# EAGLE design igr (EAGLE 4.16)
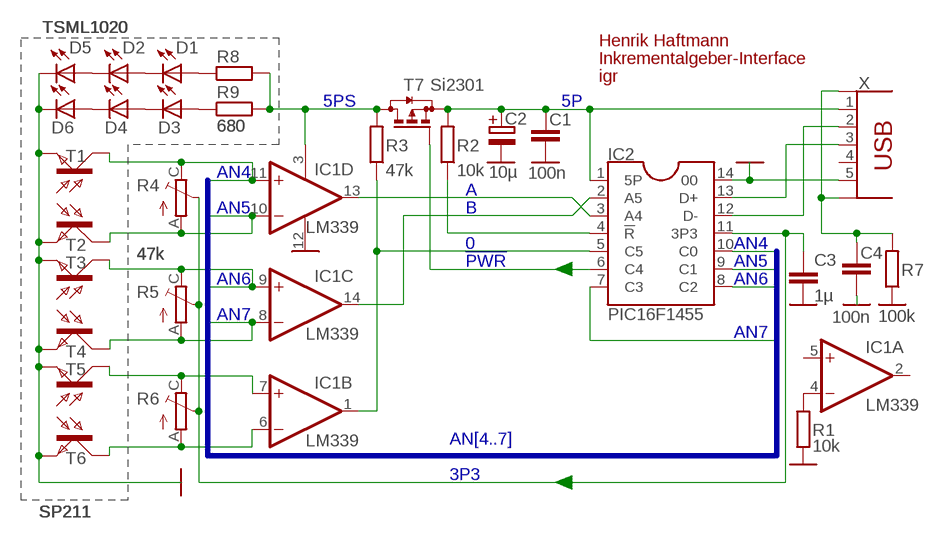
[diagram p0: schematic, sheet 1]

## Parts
C1  100n  C0603  [0603@1]
C2  10µ  E01-5  [E01-5]
C3  1µ  C0603  [0603@1]
C4  100n  C0603  [0603@1]
D1  TSML1020  LED0603  [0603]
D2  TSML1020  LED0603  [0603]
D3  TSML1020  LED0603  [0603]
D4  TSML1020  LED0603  [0603]
D5  TSML1020  LED0603  [0603]
D6  TSML1020  LED0603  [0603]
IC1  LM339  LM339N  [DIL14]
IC2  PIC16F1455  PIC16F1455-I/P  [DIL14]
R1  10k  R0603  [0603@1]
R2  10k  R0603  [0603@1]
R3  47k  R0603  [0603@1]
R4  47k  RTRIM  [RTRIM-RFT]
R5  47k  RTRIM  [RTRIM-RFT]
R6  47k  RTRIM  [RTRIM-RFT]
R7  100k  R0603  [0603@1]
R8  680  R0603  [0603@1]
R9  680  R0603  [0603@1]
T1  SP211  BPX81  [BPX81]
T2  SP211  BPX81  [BPX81]
T3  SP211  BPX81  [BPX81]
T4  SP211  BPX81  [BPX81]
T5  SP211  BPX81  [BPX81]
T6  SP211  BPX81  [BPX81]
T7  Si2301  PMOS  [SOT23]
X  USB5+2MINI  [USB-MINIB]

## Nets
0: IC1.1(B:OUT) IC2.5(C5) R3.1
3P3: C3.1 IC2.11(3P3) R4.B(S) R5.B(S) R6.B(S)
5P: C1.1 C2.+ IC2.1(5P) R2.2 T7.2(S) X.1
5PS: IC1.3(P:V+) R3.2 R8.2 R9.2 T7.3(D)
!PWR: IC2.6(C4) T7.1(G)
A: IC1.13(D:OUT) IC2.3(A4)
AN4: IC1.11(D:+IN) IC2.10(C0) R4.C(E) T1.C
AN5: IC1.10(D:-IN) IC2.9(C1) R4.A T2.C
AN6: IC1.9(C:+IN) IC2.8(C2) R5.C(E) T3.C
AN7: IC1.8(C:-IN) IC2.7(C3) R5.A T4.C
B: IC1.14(C:OUT) IC2.2(A5)
D+: IC2.13(D+) X.3
D-: IC2.12(D-) X.2
GND: C1.2 C2.- C3.2 C4.2 D5.2(K) D6.2(K) IC1.12(P:GND) IC2.14 R1.2 R7.1 T1.E T2.E T3.E T4.E T5.E T6.E X.5
N$5: IC1.4(A:-IN) R1.1
N$10: IC1.7(B:+IN) R6.C(E) T5.C
N$11: IC1.6(B:-IN) R6.A T6.C
N$14: D1.1(A) R8.1
N$15: D1.2(K) D2.1(A)
N$16: D2.2(K) D5.1(A)
N$17: D3.1(A) R9.1
N$18: D3.2(K) D4.1(A)
N$19: D4.2(K) D6.1(A)
N$26: IC2.4(!R) R2.1
PE: C4.1 R7.2 X.M1(S) X.M2(S)
Unconnected: IC1.2(A:OUT) IC1.5(A:+IN) X.4

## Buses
AN[4..7]

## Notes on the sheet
- Henrik Haftmann
- Inkrementalgeber-Interface

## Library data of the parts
C1 C3 C4 = fu:C: Kondensator
C2 = fu:E: Elektrolytkondensator, gepolt
D1-D6 = fu:LED: Leuchtdiode
IC1 = linear:LM339: Low Power Low Offset Voltage Quad Comparators with open collector; LM139/LM239/LM339/LM2901/LM3302
IC2 = hs-ul:PIC16F145*: 8-bit-Mikrocontroller mit USB Gezeichnet in Gehäuse-Anordnung, für USB-PCS500-Adapter. Typen: PIC16F1454 PIC16F1455 (mit ADU, DAU und 2x Analogvergleicher) Jeweils 8K x 14bit Flash, 1K RAM Features Benötigt keinen Quarz, interne PLL Benötigt keine USB-Serienwiderstände 3,3-V-Spannungsregler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
R1-R3 R7-R9 = fu:R: Widerstand
R4-R6 = us1:RTRIM: Einstell-Potenziometer
T1-T6 = opto-trans-siemens:BPX81: PHOTO TRANSISTOR
T7 = w:PMOS: p-Kanal-MOSFET
X = w:USB5+2: USB-Buchse (A oder B) Standardausführung der USB-Version 1.0, 4-polig Mit 2 Schirmanschlüssen

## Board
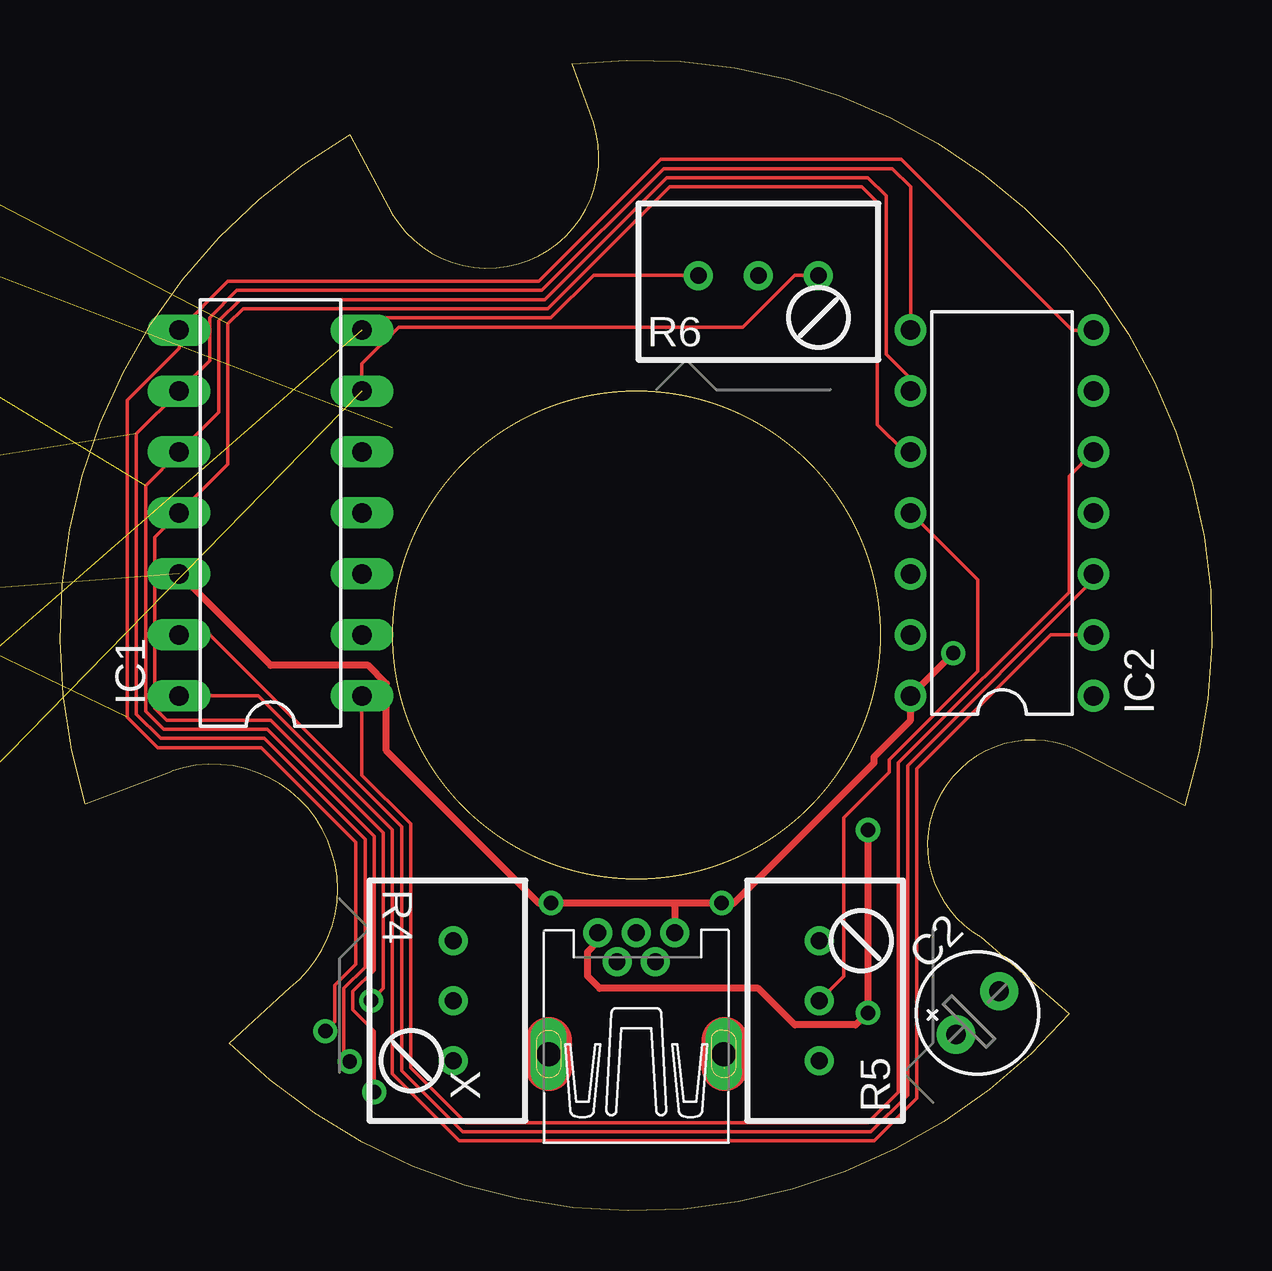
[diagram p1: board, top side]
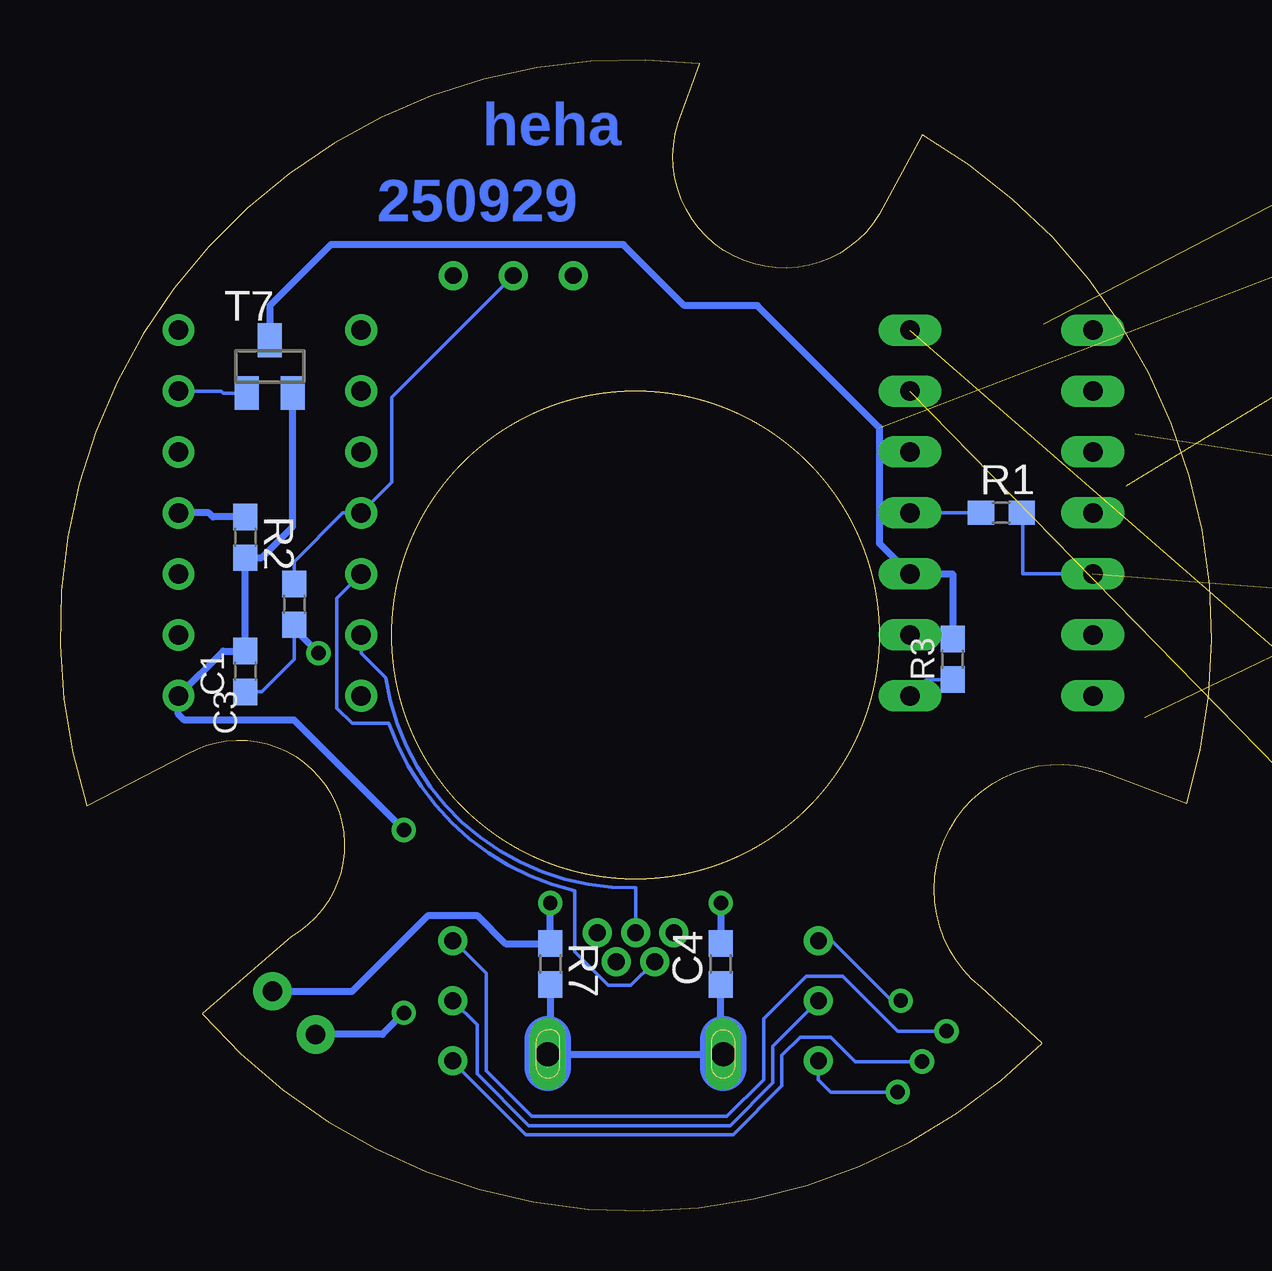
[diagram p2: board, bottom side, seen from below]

Size 47.99 x 47.96 mm. Coordinates in mm from the lower left corner, seen from the top.
Outline: 1.05,16.96 arc-77 12.07,44.83 13.85,41.53 arc167 22.23,45.34 21.34,47.8 arc-115 46.87,16.89 42.68,19.05 arc180 38.36,11.43 42.06,8.22 arc-94 7.06,6.99 9.6,9.32 arc161 4.65,18.33 1.05,16.96
Outline: circle at 24.01,24 radius 10.16
Copper layers (1*16): Top 0.035mm / dielectric 1.5mm / Bottom 0.035mm
Design rules "default": minimum track width 0.15mm, minimum drill 0.3mm, track to track 0.15mm, track to pad 0.15mm, pad to pad 0.15mm, via to via 0.15mm, smd to smd 0mil, copper to edge 0.3mm, drill to drill 0.3mm, minimum pad ring 10mil, minimum via ring 8mil, stop-mask expansion 4mil, vias tented up to drill 0mil, thermal gap 10mil
bRestrict: area 34.2,10 to 39.3,15.1; area 7.2,11 to 12.9,16.7; area 11.3,36.7 to 18.9,44.3

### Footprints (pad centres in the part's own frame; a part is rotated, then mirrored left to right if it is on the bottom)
0603@1 = smd 1.1 x 1: 1 -0.85,0; 2 0.85,0
E01-5 = drill 0.813 pad 1.6 round: + -1.27,0; - 1.27,0
0603 = smd 1.1 x 1: 1 -0.85,0; 2 0.85,0
DIL14 = drill 0.813 long: 1 -7.62,-3.81; 2 -5.08,-3.81; 3 -2.54,-3.81; 4 0,-3.81; 5 2.54,-3.81; 6 5.08,-3.81; 7 7.62,-3.81; 8 7.62,3.81; 9 5.08,3.81; 10 2.54,3.81; 11 0,3.81; 12 -2.54,3.81; 13 -5.08,3.81; 14 -7.62,3.81
DIL14' = drill 0.813 pad 1.321 round: 1 -7.62,-3.81; 2 -5.08,-3.81; 3 -2.54,-3.81; 4 0,-3.81; 5 2.54,-3.81; 6 5.08,-3.81; 7 7.62,-3.81; 8 7.62,3.81; 9 5.08,3.81; 10 2.54,3.81; 11 0,3.81; 12 -2.54,3.81; 13 -5.08,3.81; 14 -7.62,3.81
RTRIM-RFT = drill 0.7 round: A 2.5,0; B 0,0; C -2.5,0
BPX81 = drill 0.813 long: C 1.27,0; E -1.27,0
SOT23 = smd 1 x 1.4: 1 -0.95,-1.1; 2 0.95,-1.1; 3 0,1.1
USB-MINIB = drill 0.7 pad 1.016 round: 1 2.825,1.6; 2 1.625,0.8; 3 2.825,0; 4 1.625,-0.8; 5 2.825,-1.6 | drill 1 pad 1.422 long: M1 -2.225,3.65; M2 -2.225,-3.65

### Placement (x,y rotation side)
C1  40.27,22.48 270 bottom
C2  38.24,8.26 45 top
C3  38.24,25.27 270 bottom
C4  20.46,10.29 90 bottom
D1  not placed on the board
D2  not placed on the board
D3  not placed on the board
D4  not placed on the board
D5  not placed on the board
D6  not placed on the board
IC1  8.77,29.08 90 top
IC2  PIC16F1455  [DIL14']  39.25,29.08 90 top
R1  8.77,29.08 0 bottom
R2  40.27,28.07 270 bottom
R3  10.8,22.99 90 bottom
R4  16.39,8.76 270 top
R5  31.63,8.76 90 top
R6  29.1,38.97 0 top
R7  27.57,10.29 270 bottom
R8  not placed on the board
R9  not placed on the board
T1  not placed on the board
T2  not placed on the board
T3  not placed on the board
T4  not placed on the board
T5  not placed on the board
T6  not placed on the board
T7  39.25,35.18 0 bottom
X  24.01,8.76 90 top

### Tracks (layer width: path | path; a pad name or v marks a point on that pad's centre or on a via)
0
  Top 0.15: IC1.1 12.58,18.16 14.61,16.13 14.61,5.97 16.9,3.68 33.66,3.68 34.93,4.95 34.93,18.67 42.05,25.78 42.05,30.61 IC2.5
  Bottom 0.15: R3.1 11.91,22.14 IC1.1
3P3
  Top 0.15: R5.B 32.65,9.78 32.65,16.38 34.55,18.29 34.55,18.8 38.24,22.48 38.24,26.29 IC2.11
  Bottom 0.15: C3.1 38.24,27.05 36.2,29.08 IC2.11 34.17,30.35 34.17,33.91 R6.B | R4.B 18.3,6.86 18.3,5.34 20.07,3.56 28.46,3.56 30.62,5.72 30.62,7.75 R5.B
5P  (via drill 0.6)
  Top 0.3: X.1 22.41,11.23 21.98,10.8 21.98,9.78 22.49,9.27 29.09,9.27 30.62,7.75 33.16,7.75 v33.66,8.26 v33.66,15.88
  Bottom 0.3: C2.+ 34.56,7.36 v33.66,8.26 | v33.66,15.88 38.24,20.45 42.81,20.45 43.06,20.7 IC2.1 41.2,23.33 C1.1 R2.2 39.59,27.22 38.3,28.51 T7.2
5PS  (2 unrouted)
  Bottom 0.3: T7.3 39.25,37.72 36.71,40.26 24.52,40.26 21.98,37.72 18.93,37.72 13.85,32.64 13.85,27.81 IC1.3 10.8,26.54 R3.2
!PWR
  Bottom 0.15: T7.1 41.2,34.08 41.28,34.16 IC2.6
A
  Top 0.15: IC1.13 6.23,24 14.23,16 14.23,5.84 16.77,3.3 33.79,3.3 35.31,4.83 35.31,18.54 43.06,26.29 IC2.3
AN4  (via drill 0.6)  (1 unrouted)
  Top 0.15: v12.96,8.76 13.47,9.27 13.47,15.75 8.77,20.45 4.45,20.45 3.95,20.96 3.95,28.07 IC1.11 6.99,31.12 6.99,36.96 7.63,37.59 20.33,37.59 25.41,42.67 33.41,42.67 34.04,42.04 34.04,32.77 35.19,31.62 IC2.10
  Bottom 0.15: v12.96,8.76 13.34,8.76 15.88,11.3 16.39,11.3 R4.C
AN5  (via drill 0.6)  (1 unrouted)
  Top 0.15: v13.09,4.95 13.09,7.49 12.2,8.38 12.2,9.15 13.09,10.03 13.09,15.62 8.64,20.07 4.33,20.07 3.56,20.83 3.56,30.23 IC1.10 6.61,33.28 6.61,37.09 7.5,37.97 20.2,37.97 25.28,43.05 33.66,43.05 34.43,42.29 34.43,35.69 35.44,34.67 IC2.9
  Bottom 0.15: v13.09,4.95 15.88,4.95 16.39,5.46 R4.A
AN6  (via drill 0.6)  (1 unrouted)
  Top 0.15: v12.07,6.22 11.82,6.48 11.82,9.27 12.71,10.16 12.71,15.5 8.52,19.69 4.2,19.69 3.18,20.7 3.18,32.39 IC1.9 6.23,35.43 6.23,37.21 7.37,38.36 20.07,38.36 25.15,43.44 34.68,43.44 35.44,42.67 IC2.8
  Bottom 0.15: v12.07,6.22 14.87,6.22 15.88,7.24 17.15,7.24 17.92,6.48 17.92,5.21 19.95,3.18 28.58,3.18 31.63,6.22 R5.C
AN7  (via drill 0.6)  (1 unrouted)
  Top 0.15: v11.06,7.49 11.44,7.88 11.44,9.4 12.33,10.29 12.33,15.37 8.39,19.31 4.07,19.31 2.8,20.58 2.8,33.78 4.96,35.94 IC1.8 6.99,38.74 19.95,38.74 25.03,43.82 35.06,43.82 42.17,36.7 IC2.7
  Bottom 0.15: v11.06,7.49 13.09,7.49 15.38,9.78 16.9,9.78 18.68,8 18.68,5.46 20.2,3.94 28.33,3.94 30.23,5.84 30.23,9.91 31.63,11.3 R5.A
B
  Top 0.15: IC1.14 8.26,21.46 13.85,15.88 13.85,5.72 16.65,2.92 33.92,2.92 35.7,4.7 35.7,18.42 41.28,24 IC2.2
D+
  Bottom 0.15: X.3 24.01,13.46 arc83 34.43,22.23 35.44,23.24 IC2.13
D-
  Bottom 0.15: IC2.12 36.46,25.53 36.46,20.96 35.82,20.32 34.3,20.32 arc-57 26.55,13.34 26.55,10.8 25.15,9.4 24.2,9.4 X.2
GND  (via drill 0.6)  (8 unrouted)
  Top 0.3: X.5 25.61,12.75 25.54,12.83 | 25.54,12.83 v20.46,12.83 19.95,12.83 13.6,19.18 13.6,21.97 12.84,22.73 8.77,22.73 IC1.12 | 25.54,12.83 v27.57,12.83 28.08,12.83 33.92,18.67 33.92,18.92 35.44,20.45 IC2.14 v37.22,23.24
  Bottom 0.15: C3.2 38.24,22.99 39.59,21.63 C1.2 | R1.2 7.88,29.08 7.88,26.54 IC1.12
  Bottom 0.3: v20.46,12.83 C4.2 | v27.57,12.83 R7.1 29.43,11.14 30.62,12.32 32.65,12.32 35.82,9.15 C2.- | C2.- | C3.2 38.24,24.26 v37.22,23.24
N$5
  Bottom 0.15: IC1.4 R1.1
N$10  (1 unrouted)
  Top 0.15: IC1.7 13.09,37.21 20.46,37.21 22.23,38.99 26.55,38.99 26.57,38.97 R6.C
N$11  (1 unrouted)
  Top 0.15: IC1.6 12.58,35.31 14.11,36.83 28.46,36.83 30.62,38.99 31.5,38.99 31.52,38.97 R6.A
N$14  (1 unrouted)
N$15  (1 unrouted)
N$16  (1 unrouted)
N$17  (1 unrouted)
N$18  (1 unrouted)
N$19  (1 unrouted)
N$26
  Bottom 0.3: R2.1 41.63,28.92 41.79,29.08 IC2.4
PE  (1 unrouted)
  Top 1.93: 20.36,7.11 X.M1 20.36,5.97 | 27.69,7.11 27.69,5.97
  Bottom 0.3: 20.36,7.15 20.46,7.24 C4.1 | 27.66,7.15 27.57,7.24 R7.2 | X.M2 X.M1
  Bottom 1.93: 20.36,7.15 X.M1 20.36,5.97 | 27.66,7.15 X.M2 27.66,5.97

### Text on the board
Bottom: heha | 250929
